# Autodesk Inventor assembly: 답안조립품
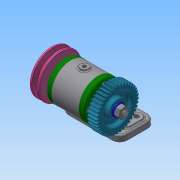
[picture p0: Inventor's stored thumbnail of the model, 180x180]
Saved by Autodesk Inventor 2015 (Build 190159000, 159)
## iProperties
Created: 2023-08
Part Number: 답안조립품
Document SubType Name: Assembly
Designer: 학생용
Author: 학생용
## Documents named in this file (12)
- C:\Users\학생용\Desktop\730806V1008\답안조립품.iam
- C:\Users\학생용\Desktop\730806V1008\본체.ipt
- C:\Users\학생용\Desktop\730806V1008\커버.ipt
- C:\Users\학생용\Desktop\730806V1008\오일실 20x35x8.ipt
- C:\Users\학생용\Desktop\730806V1008\베어링 6204.ipt
- C:\Users\학생용\Desktop\730806V1008\축.ipt
- C:\Users\학생용\Desktop\730806V1008\키 5x5.ipt
- C:\Users\학생용\Desktop\730806V1008\스퍼기어.ipt
- C:\Users\학생용\Desktop\730806V1008\V벨트풀리.ipt
- C:\Users\학생용\Desktop\730806V1008\와셔 12x24.ipt
- C:\Users\학생용\Desktop\730806V1008\너트 M12x1.25.ipt
- C:\Users\학생용\Desktop\730806V1008\볼트 M4 x 12.ipt
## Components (1 placed, 1 different names)
1. V벨트풀리:1 — 각도:2
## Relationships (1: Angle 1)
- 각도:2 [Angle]: V벨트풀리:1
